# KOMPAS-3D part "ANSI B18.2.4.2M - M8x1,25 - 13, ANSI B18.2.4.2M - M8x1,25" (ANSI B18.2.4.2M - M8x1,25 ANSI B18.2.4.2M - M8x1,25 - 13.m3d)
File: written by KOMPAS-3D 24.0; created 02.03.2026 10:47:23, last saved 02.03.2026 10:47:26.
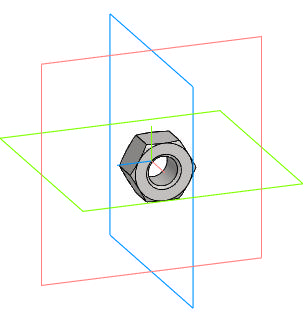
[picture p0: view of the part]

Document properties: Автор: R2D2; Полное имя файла: E:\Работа\Зайцев\GVWR3131M-2W-F-S Задвижка клиновая с выдвижным штоком DN.ru Ду50-200 Ру63\DN200\исходные материалы\ANSI B18.2.4.2M - M8x1,25 ANSI B18.2.4.2M - M8x1,25 - 13.m3d

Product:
- Body: Solid1  | qty 1
    Масса: 0.006562
- Body: Solid1  | qty 1
    Масса: 0.006562
- Part/product: ANSI B18.2.4.2M - M8x1,25 - 13  | designation ANSI B18.2.4.2M - M8x1,25
    Масса: 0.006562
    Комментарий: Типы метрических   шестигранных гаек   2
    additional columns: Сталь, мягкая
- Part/product: ANSI B18.2.4.2M - M8x1,25 - 13  | designation ANSI B18.2.4.2M - M8x1,25-01
    Масса: 0.006562
    Комментарий: Типы метрических   шестигранных гаек   2
    additional columns: Сталь, мягкая

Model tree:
1. Solid1  (labels: Solid1)

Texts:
  ANSI B18.2.4.2M - M8x1,25
  ANSI B18.2.4.2M - M8x1,25-01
